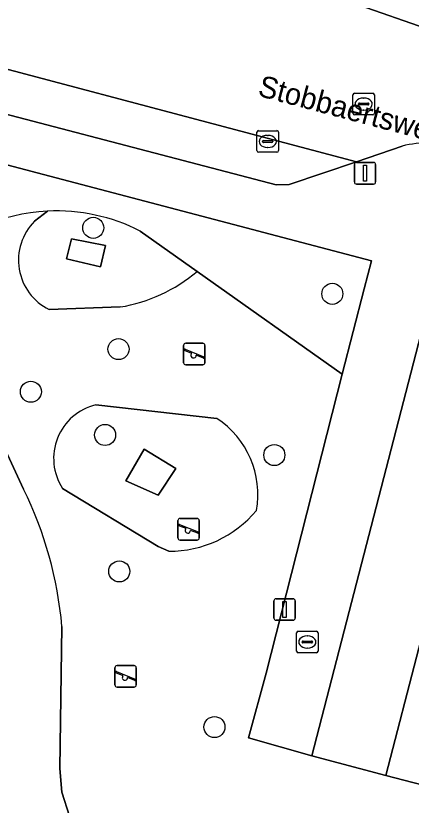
# Model space of a CAD drawing. Extents: x 163683 to 164494, y 382709 to 383872.
# Drawn here: x 163955.82 to 163974.2, y 383144.43 to 383181.08 of the extents above; entities that cross this region are included whole.
import ezdxf

# ---------------------------------------------------------------- set-up
doc = ezdxf.new("R2010")
doc.units = 0
for name, color, linetype in [('IMGEO_Boom', 7, 'Continuous'), ('IMGEO_Brandkraan', 7, 'Continuous'), ('IMGEO_Erf', 7, 'Continuous'), ('IMGEO_Groenvoorziening', 7, 'Continuous'), ('IMGEO_Kolk', 7, 'Continuous'), ('IMGEO_Lichtmast', 7, 'Continuous'), ('IMGEO_Openbare_ruimte_label', 7, 'Continuous'), ('IMGEO_Pand', 7, 'Continuous'), ('IMGEO_Parkeervlak_open', 7, 'Continuous'), ('IMGEO_Rijbaan_lokaal_open', 7, 'Continuous'), ('IMGEO_Rioolput', 7, 'Continuous'), ('IMGEO_Speelvoorziening', 7, 'Continuous'), ('IMGEO_Voetpad_halfverhard', 7, 'Continuous'), ('IMGEO_Voetpad_open', 7, 'Continuous')]:
    doc.layers.add(name, color=color, linetype=linetype)

msp = doc.modelspace()

# ---------------------------------------------------------------- linework, layer by layer
at = {"layer": 'IMGEO_Boom'}
for centre in [(163959.423, 383171.239), (163970.537, 383168.173), (163960.597, 383165.606), (163956.524, 383163.627), (163959.975, 383161.62), (163967.841, 383160.688), (163960.634, 383155.285), (163965.059, 383148.058)]:
    msp.add_circle(centre, 0.489, dxfattribs=at)
at = {"layer": 'IMGEO_Brandkraan'}
for p, q in [((163968.949, 383152.507), (163969.801, 383152.507)), ((163968.874, 383151.581), (163968.874, 383152.433)), ((163969.362, 383152.287), (163969.387, 383152.287)), ((163969.875, 383152.433), (163969.875, 383151.581)), ((163969.133, 383152.001), (163969.133, 383152.013)), ((163969.571, 383151.964), (163969.173, 383151.964)), ((163969.176, 383152.05), (163969.574, 383152.05)), ((163969.617, 383152.013), (163969.617, 383152.001)), ((163969.801, 383151.507), (163968.949, 383151.507)), ((163969.385, 383151.727), (163969.36, 383151.727))]:
    msp.add_line(p, q, dxfattribs=at)
for points in [[(163968.949, 383152.507), (163969.801, 383152.507)], [(163968.874, 383151.581), (163968.874, 383152.433)], [(163969.875, 383152.433), (163969.875, 383151.581)], [(163969.801, 383151.507), (163968.949, 383151.507)]]:
    msp.add_lwpolyline(points, dxfattribs=at)
for centre, radius, start, end in [((163968.951, 383152.431), 0.0765, 91.552, 178.448), ((163968.951, 383152.431), 0.0765, 91.552, 178.448), ((163969.799, 383152.431), 0.0765, 1.552, 88.448), ((163969.799, 383152.431), 0.0765, 1.552, 88.448), ((163969.173, 383152.01), 0.0403, 85.8775, 175.7526), ((163969.17, 383152), 0.0366, 178.938, 274.7102), ((163969.574, 383152.007), 0.043, 264.8664, 352.4533), ((163969.578, 383152.012), 0.0386, 1.7309, 96.639), ((163968.951, 383151.583), 0.0765, 181.552, 268.448), ((163968.951, 383151.583), 0.0765, 181.552, 268.448), ((163969.799, 383151.583), 0.0765, 271.552, 358.448), ((163969.799, 383151.583), 0.0765, 271.552, 358.448)]:
    msp.add_arc(centre, radius, start, end, dxfattribs=at)
for centre, major_axis, ratio, start_param, end_param in [((163969.361, 383152.007), (-0.387, 0.002), 0.722429, 4.712389, 7.853982), ((163969.386, 383152.007), (-0.39, 0.002), 0.717154, 1.570796, 4.712389)]:
    msp.add_ellipse(centre, major_axis=major_axis, ratio=ratio, start_param=start_param, end_param=end_param, dxfattribs=at)
at = {"layer": 'IMGEO_Erf'}
msp.add_lwpolyline([(163973.026, 383145.81), (163974.56, 383151.722), (163976.088, 383157.611), (163977.604, 383163.456), (163979.145, 383169.396), (163975.685, 383170.296), (163969.581, 383146.721)], close=True, dxfattribs=at)
at = {"layer": 'IMGEO_Groenvoorziening'}
for points in [[(163972.356, 383169.703), (163951.272, 383175.245), (163950.92, 383174.073), (163950.792, 383172.833), (163950.901, 383171.592), (163951.234, 383170.414), (163951.628, 383169.458)], [(163957.3, 383172.011), (163956.694, 383171.542)], [(163956.694, 383171.542), (163957.3, 383172.011)], [(163964.25, 383169.215), (163961.604, 383171.089)], [(163961.604, 383171.089), (163964.25, 383169.215), (163970.996, 383164.436), (163972.015, 383168.411), (163972.356, 383169.703)], [(163951.628, 383169.458), (163953.586, 383164.707), (163956.187, 383159.108)], [(163970.996, 383164.436), (163964.25, 383169.215)], [(163957.374, 383167.444), (163960.669, 383167.563)], [(163960.669, 383167.563), (163957.374, 383167.444)], [(163957.967, 383152.728), (163957.872, 383146.141), (163957.969, 383145.037), (163958.314, 383143.913), (163958.92, 383142.853), (163959.759, 383141.944), (163960.768, 383141.256), (163961.861, 383140.822), (163962.954, 383140.638), (163968.854, 383140.139), (163974.734, 383139.412), (163979.255, 383138.674), (163980.317, 383143.919), (163973.026, 383145.81), (163969.581, 383146.721), (163966.645, 383147.557), (163967.46, 383150.553), (163970.996, 383164.436)], [(163965.162, 383162.389), (163959.539, 383163.015)], [(163959.539, 383163.015), (163965.162, 383162.389)], [(163957.997, 383159.142), (163962.444, 383156.444), (163962.933, 383156.219)], [(163962.933, 383156.219), (163962.444, 383156.444), (163957.997, 383159.142)]]:
    msp.add_lwpolyline(points, dxfattribs=at)
for points in [[(163959.989, 383170.421), (163958.417, 383170.722), (163958.173, 383169.806), (163959.76, 383169.421)], [(163959.76, 383169.421), (163958.173, 383169.806), (163958.417, 383170.722), (163959.989, 383170.421)], [(163963.258, 383160.061), (163961.796, 383160.966), (163960.935, 383159.487), (163962.444, 383158.829)], [(163962.444, 383158.829), (163960.935, 383159.487), (163961.796, 383160.966), (163963.258, 383160.061)]]:
    msp.add_lwpolyline(points, close=True, dxfattribs=at)
for centre, radius, start, end in [((163957.723, 383163.494), 8.528, 92.8434, 135.6222), ((163957.723, 383163.494), 8.528, 92.8434, 135.6222), ((163957.723, 383163.477), 8.544, 62.9822, 92.8356), ((163957.723, 383163.477), 8.544, 62.9822, 92.8356), ((163958.506, 383169.737), 2.557, 135.1148, 243.7282), ((163958.506, 383169.737), 2.557, 135.1148, 243.7282), ((163959.51, 383174.782), 7.311, 279.1187, 310.4113), ((163959.51, 383174.782), 7.311, 279.1187, 310.4113), ((163960.131, 383160.536), 2.549, 103.428, 213.153), ((163960.131, 383160.536), 2.549, 103.428, 213.153), ((163962.867, 383158.862), 4.208, 349.6947, 56.9446), ((163962.867, 383158.862), 4.208, 349.6947, 56.9446), ((163939.978, 383151.147), 18.058, 5.0213, 26.1566), ((163962.954, 383161.509), 5.29, 269.771, 320.0038), ((163962.954, 383161.509), 5.29, 269.771, 320.0038)]:
    msp.add_arc(centre, radius, start, end, dxfattribs=at)
at = {"layer": 'IMGEO_Kolk'}
for p, q in [((163967.034, 383174.823), (163967.034, 383175.675)), ((163967.109, 383175.749), (163967.961, 383175.749)), ((163968.035, 383175.675), (163968.035, 383174.823)), ((163967.293, 383175.243), (163967.293, 383175.255)), ((163967.336, 383175.292), (163967.734, 383175.292)), ((163967.522, 383175.529), (163967.547, 383175.529)), ((163967.777, 383175.255), (163967.777, 383175.243)), ((163967.731, 383175.206), (163967.333, 383175.206)), ((163967.545, 383174.969), (163967.52, 383174.969)), ((163967.961, 383174.749), (163967.109, 383174.749))]:
    msp.add_line(p, q, dxfattribs=at)
for points in [[(163967.034, 383174.823), (163967.034, 383175.675)], [(163967.109, 383175.749), (163967.961, 383175.749)], [(163968.035, 383175.675), (163968.035, 383174.823)], [(163967.961, 383174.749), (163967.109, 383174.749)]]:
    msp.add_lwpolyline(points, dxfattribs=at)
for centre, radius, start, end in [((163967.111, 383175.673), 0.0765, 91.552, 178.448), ((163967.111, 383175.673), 0.0765, 91.552, 178.448), ((163967.959, 383175.673), 0.0765, 1.552, 88.448), ((163967.959, 383175.673), 0.0765, 1.552, 88.448), ((163967.333, 383175.252), 0.0403, 85.8775, 175.7526), ((163967.33, 383175.242), 0.0366, 178.938, 274.7102), ((163967.734, 383175.249), 0.043, 264.8664, 352.4533), ((163967.738, 383175.254), 0.0386, 1.7309, 96.639), ((163967.111, 383174.825), 0.0765, 181.552, 268.448), ((163967.111, 383174.825), 0.0765, 181.552, 268.448), ((163967.959, 383174.825), 0.0765, 271.552, 358.448), ((163967.959, 383174.825), 0.0765, 271.552, 358.448)]:
    msp.add_arc(centre, radius, start, end, dxfattribs=at)
for centre, major_axis, ratio, start_param, end_param in [((163967.521, 383175.249), (-0.387, 0.002), 0.722429, 4.712389, 7.853982), ((163967.546, 383175.249), (-0.39, 0.002), 0.717154, 1.570796, 4.712389)]:
    msp.add_ellipse(centre, major_axis=major_axis, ratio=ratio, start_param=start_param, end_param=end_param, dxfattribs=at)
at = {"layer": 'IMGEO_Lichtmast'}
for p, q in [((163971.561, 383173.372), (163971.561, 383174.172)), ((163971.561, 383174.172), (163971.561, 383173.372)), ((163971.661, 383174.272), (163972.451, 383174.272)), ((163972.451, 383174.272), (163971.661, 383174.272)), ((163972.551, 383174.172), (163972.551, 383173.372)), ((163972.551, 383173.372), (163972.551, 383174.172)), ((163972.451, 383173.272), (163971.661, 383173.272)), ((163971.661, 383173.272), (163972.451, 383173.272)), ((163967.92, 383154.016), (163968.71, 383154.016)), ((163968.71, 383154.016), (163967.92, 383154.016)), ((163967.82, 383153.116), (163967.82, 383153.916)), ((163967.82, 383153.916), (163967.82, 383153.116)), ((163968.81, 383153.916), (163968.81, 383153.116)), ((163968.81, 383153.116), (163968.81, 383153.916)), ((163968.71, 383153.016), (163967.92, 383153.016)), ((163967.92, 383153.016), (163968.71, 383153.016))]:
    msp.add_line(p, q, dxfattribs=at)
for points in [[(163971.981, 383174.147), (163972.131, 383174.147), (163972.131, 383173.397), (163971.981, 383173.397), (163971.981, 383174.147)], [(163968.24, 383153.891), (163968.39, 383153.891), (163968.39, 383153.141), (163968.24, 383153.141), (163968.24, 383153.891)]]:
    msp.add_lwpolyline(points, dxfattribs=at)
for centre, start, end in [((163971.661, 383174.172), 90, 180), ((163971.661, 383174.172), 90, 180), ((163972.451, 383174.172), 0, 90), ((163972.451, 383174.172), 360, 90), ((163971.661, 383173.372), 180, 270), ((163971.661, 383173.372), 180, 270), ((163972.451, 383173.372), 270, 0), ((163972.451, 383173.372), 270, 0), ((163967.92, 383153.916), 90, 180), ((163967.92, 383153.916), 90, 180), ((163968.71, 383153.916), 0, 90), ((163968.71, 383153.916), 360, 90), ((163967.92, 383153.116), 180, 270), ((163967.92, 383153.116), 180, 270), ((163968.71, 383153.116), 270, 0), ((163968.71, 383153.116), 270, 0)]:
    msp.add_arc(centre, 0.1, start, end, dxfattribs=at)
at = {"layer": 'IMGEO_Pand'}
msp.add_lwpolyline([(163974.56, 383151.722), (163973.026, 383145.81), (163980.317, 383143.919), (163981.37, 383143.646), (163982.109, 383146.493), (163983.234, 383146.201), (163984.03, 383149.269)], close=True, dxfattribs=at)
at = {"layer": 'IMGEO_Parkeervlak_open'}
msp.add_lwpolyline([(163950.263, 383177.852), (163967.921, 383173.229), (163968.531, 383173.244), (163971.666, 383174.303), (163947.794, 383180.623)], dxfattribs=at)
at = {"layer": 'IMGEO_Rijbaan_lokaal_open'}
for points in [[(163970.365, 383182.091), (163976.318, 383179.994)], [(163976.318, 383179.994), (163970.365, 383182.091)], [(163947.794, 383180.623), (163971.666, 383174.303), (163973.785, 383175.031)]]:
    msp.add_lwpolyline(points, dxfattribs=at)
msp.add_arc((163974.946, 383170.456), 4.72, 72.355, 104.2418, dxfattribs=at)
at = {"layer": 'IMGEO_Rioolput'}
for p, q in [((163971.567, 383177.485), (163972.419, 383177.485)), ((163971.492, 383176.559), (163971.492, 383177.411)), ((163971.98, 383177.265), (163972.005, 383177.265)), ((163972.493, 383177.411), (163972.493, 383176.559)), ((163971.751, 383176.979), (163971.751, 383176.991)), ((163972.189, 383176.942), (163971.791, 383176.942)), ((163971.794, 383177.028), (163972.192, 383177.028)), ((163972.003, 383176.705), (163971.978, 383176.705)), ((163972.235, 383176.991), (163972.235, 383176.979)), ((163972.419, 383176.485), (163971.567, 383176.485))]:
    msp.add_line(p, q, dxfattribs=at)
for points in [[(163971.567, 383177.485), (163972.419, 383177.485)], [(163971.492, 383176.559), (163971.492, 383177.411)], [(163972.493, 383177.411), (163972.493, 383176.559)], [(163972.419, 383176.485), (163971.567, 383176.485)]]:
    msp.add_lwpolyline(points, dxfattribs=at)
for centre, radius, start, end in [((163971.569, 383177.409), 0.0765, 91.552, 178.448), ((163971.569, 383177.409), 0.0765, 91.552, 178.448), ((163972.417, 383177.409), 0.0765, 1.552, 88.448), ((163972.417, 383177.409), 0.0765, 1.552, 88.448), ((163971.791, 383176.988), 0.0403, 85.8775, 175.7526), ((163971.788, 383176.978), 0.0366, 178.938, 274.7102), ((163972.192, 383176.985), 0.043, 264.8664, 352.4533), ((163972.196, 383176.99), 0.0386, 1.7309, 96.639), ((163971.569, 383176.561), 0.0765, 181.552, 268.448), ((163971.569, 383176.561), 0.0765, 181.552, 268.448), ((163972.417, 383176.561), 0.0765, 271.552, 358.448), ((163972.417, 383176.561), 0.0765, 271.552, 358.448)]:
    msp.add_arc(centre, radius, start, end, dxfattribs=at)
for centre, major_axis, ratio, start_param, end_param in [((163971.979, 383176.985), (-0.387, 0.002), 0.722429, 4.712389, 7.853982), ((163972.004, 383176.985), (-0.39, 0.002), 0.717154, 1.570796, 4.712389)]:
    msp.add_ellipse(centre, major_axis=major_axis, ratio=ratio, start_param=start_param, end_param=end_param, dxfattribs=at)
at = {"layer": 'IMGEO_Speelvoorziening'}
for p, q in [((163963.623, 383164.977), (163963.623, 383165.777)), ((163963.623, 383165.777), (163963.623, 383164.977)), ((163963.723, 383165.877), (163964.513, 383165.877)), ((163964.513, 383165.877), (163963.723, 383165.877)), ((163964.613, 383165.777), (163964.613, 383164.977)), ((163964.613, 383164.977), (163964.613, 383165.777)), ((163964.006, 383165.405), (163963.667, 383165.542)), ((163963.692, 383165.602), (163964.568, 383165.249)), ((163964.544, 383165.189), (163964.204, 383165.326)), ((163964.513, 383164.877), (163963.723, 383164.877)), ((163963.723, 383164.877), (163964.513, 383164.877)), ((163963.358, 383156.843), (163963.358, 383157.643)), ((163963.358, 383157.643), (163963.358, 383156.843)), ((163963.458, 383157.743), (163964.248, 383157.743)), ((163964.248, 383157.743), (163963.458, 383157.743)), ((163964.348, 383157.643), (163964.348, 383156.843)), ((163964.348, 383156.843), (163964.348, 383157.643)), ((163963.741, 383157.271), (163963.402, 383157.408)), ((163963.427, 383157.468), (163964.303, 383157.115)), ((163964.279, 383157.055), (163963.939, 383157.192)), ((163964.248, 383156.743), (163963.458, 383156.743)), ((163963.458, 383156.743), (163964.248, 383156.743)), ((163960.432, 383150.015), (163960.432, 383150.815)), ((163960.432, 383150.815), (163960.432, 383150.015)), ((163960.532, 383150.915), (163961.322, 383150.915)), ((163961.322, 383150.915), (163960.532, 383150.915)), ((163961.422, 383150.815), (163961.422, 383150.015)), ((163961.422, 383150.015), (163961.422, 383150.815)), ((163960.815, 383150.443), (163960.476, 383150.58)), ((163960.501, 383150.64), (163961.377, 383150.287)), ((163961.353, 383150.227), (163961.013, 383150.364)), ((163961.322, 383149.915), (163960.532, 383149.915)), ((163960.532, 383149.915), (163961.322, 383149.915))]:
    msp.add_line(p, q, dxfattribs=at)
for centre, radius, start, end in [((163963.723, 383165.777), 0.1, 90, 180), ((163963.723, 383165.777), 0.1, 90, 180), ((163964.513, 383165.777), 0.1, 0, 90), ((163964.513, 383165.777), 0.1, 360, 90), ((163963.68, 383165.572), 0.0327, 68.078, 248.078), ((163964.085, 383165.315), 0.12, 130.9928, 5.1632), ((163963.723, 383164.977), 0.1, 180, 270), ((163963.723, 383164.977), 0.1, 180, 270), ((163964.513, 383164.977), 0.1, 270, 0), ((163964.513, 383164.977), 0.1, 270, 0), ((163964.556, 383165.219), 0.0327, 248.078, 68.078), ((163963.458, 383157.643), 0.1, 90, 180), ((163963.458, 383157.643), 0.1, 90, 180), ((163964.248, 383157.643), 0.1, 0, 90), ((163964.248, 383157.643), 0.1, 360, 90), ((163963.415, 383157.438), 0.0327, 68.078, 248.078), ((163963.82, 383157.181), 0.12, 130.9928, 5.1632), ((163964.291, 383157.085), 0.0327, 248.078, 68.078), ((163963.458, 383156.843), 0.1, 180, 270), ((163963.458, 383156.843), 0.1, 180, 270), ((163964.248, 383156.843), 0.1, 270, 0), ((163964.248, 383156.843), 0.1, 270, 0), ((163960.532, 383150.815), 0.1, 90, 180), ((163960.532, 383150.815), 0.1, 90, 180), ((163961.322, 383150.815), 0.1, 0, 90), ((163961.322, 383150.815), 0.1, 360, 90), ((163960.489, 383150.61), 0.0327, 68.078, 248.078), ((163960.894, 383150.353), 0.12, 130.9928, 5.1632), ((163960.532, 383150.015), 0.1, 180, 270), ((163960.532, 383150.015), 0.1, 180, 270), ((163961.322, 383150.015), 0.1, 270, 0), ((163961.322, 383150.015), 0.1, 270, 0), ((163961.365, 383150.257), 0.0327, 248.078, 68.078)]:
    msp.add_arc(centre, radius, start, end, dxfattribs=at)
at = {"layer": 'IMGEO_Voetpad_halfverhard'}
for points in [[(163956.187, 383159.108), (163953.586, 383164.707)], [(163986.383, 383137.276), (163980.581, 383138.456), (163979.255, 383138.674), (163974.734, 383139.412), (163968.854, 383140.139), (163962.954, 383140.638), (163961.861, 383140.822), (163960.768, 383141.256), (163959.759, 383141.944), (163958.92, 383142.853), (163958.314, 383143.913), (163957.969, 383145.037), (163957.872, 383146.141), (163957.967, 383152.728)]]:
    msp.add_lwpolyline(points, dxfattribs=at)
msp.add_arc((163939.978, 383151.147), 18.058, 5.0213, 26.1566, dxfattribs=at)
at = {"layer": 'IMGEO_Voetpad_open'}
for points in [[(163945.758, 383180.783), (163944.588, 383176.258), (163945.37, 383176.797), (163947.072, 383176.35), (163951.272, 383175.245), (163972.356, 383169.703), (163972.015, 383168.411), (163970.996, 383164.436), (163967.46, 383150.553), (163966.645, 383147.557), (163969.581, 383146.721), (163975.685, 383170.296)], [(163973.785, 383175.031), (163971.666, 383174.303), (163968.531, 383173.244), (163967.921, 383173.229), (163950.263, 383177.852)]]:
    msp.add_lwpolyline(points, dxfattribs=at)
msp.add_arc((163974.946, 383170.456), 4.72, 72.355, 104.2418, dxfattribs=at)

# ---------------------------------------------------------------- texts
at = {"layer": 'IMGEO_Openbare_ruimte_label'}
msp.add_text('Stobbaertsweg', height=1, rotation=345.2273, dxfattribs=at).set_placement((163967.026, 383177.377))

doc.saveas('drawing.dxf')
